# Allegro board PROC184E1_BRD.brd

Outline 248.76 x 190.5 mm; copper layers: TOP, L2-GND1, L3-SIGNAL1, L4-GND2, L5-SIGNAL2, L6-GND3, L7-SIGNAL3, L8-PWR1, L9-PWR2, L10-SIGNAL4, L11-GND4, L12-SIGNAL5, L13-GND5, L14-SIGNAL6, L15-GND6, BOTTOM. Coordinates in mm from the lower left corner of the outline.
Outline path: 5,190.5 0,190.5 0,0 5,0 ; 5,190.5 5,0 ; 5,190.5 16.79,190.5 17.29,190 17.29,188.93 arc(17.72,188.45) 18.19,188.9 18.19,190 18.69,190.5 21.54,190.5 22.04,190 22.04,188.89 arc(22.49,188.45) 22.94,188.9 22.94,190 23.44,190.5 243.76,190.5 ; 5,0 184.81,0 185.31,0.5 185.31,1.6 arc(185.76,2.05) 186.21,1.6 186.21,0.5 186.71,0 189.56,0 190.06,0.5 190.06,1.6 arc(190.51,2.05) 190.96,1.6 190.96,0.5 191.46,0 205.41,0 205.91,0.5 205.91,1.6 arc(206.36,2.05) 206.81,1.6 206.81,0.5 207.31,0 210.16,0 210.66,0.5 210.66,1.6 arc(211.11,2.05) 211.56,1.6 211.56,0.5 212.06,0 243.76,0 ; 243.76,0 243.76,190.5 ; 243.76,0 248.76,0 248.76,190.5 243.76,190.5

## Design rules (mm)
net group 33-OHM_PH: nets DDR0_CA1 DDR0_CA5
net group AOUT1: nets AOUT1_N AOUT1_P
net group AOUT2: nets AOUT2_N AOUT2_P
net group C_DP0_AUX_N: nets C_DP0_AUX_N DP0_AUX_N
net group C_DP0_AUX_P: nets C_DP0_AUX_P DP0_AUX_P
net group C_DP0_TX0_N: nets C_DP0_TX0_N DP0_TX0_N
net group C_DP0_TX0_P: nets C_DP0_TX0_P DP0_TX0_P
net group C_DP0_TX1_N: nets C_DP0_TX1_N DP0_TX1_N
net group C_DP0_TX1_P: nets C_DP0_TX1_P DP0_TX1_P
net group C_DP0_TX2_N: nets C_DP0_TX2_N DP0_TX2_N
net group C_DP0_TX2_P: nets C_DP0_TX2_P DP0_TX2_P
net group C_DP0_TX3_N: nets C_DP0_TX3_N DP0_TX3_N
net group C_DP0_TX3_P: nets C_DP0_TX3_P DP0_TX3_P
net group C_DP1_AUX_N: nets C_DP1_AUX_N DP1_AUX_N
net group C_DP1_AUX_P: nets C_DP1_AUX_P DP1_AUX_P
net group C_DP1_TX0_N: nets C_DP1_TX0_N DP1_TX0_N
net group C_DP1_TX0_P: nets C_DP1_TX0_P DP1_TX0_P
net group C_DP1_TX1_N: nets C_DP1_TX1_N DP1_TX1_N
net group C_DP1_TX1_P: nets C_DP1_TX1_P DP1_TX1_P
net group C_DP1_TX2_N: nets C_DP1_TX2_N DP1_TX2_N
net group C_DP1_TX2_P: nets C_DP1_TX2_P DP1_TX2_P
net group C_DP1_TX3_N: nets C_DP1_TX3_N DP1_TX3_N
net group C_DP1_TX3_P: nets C_DP1_TX3_P DP1_TX3_P
net group C_PCIE0_TX0_N: nets C_PCIE0_TX0_N PCIE0_TX0_N
net group C_PCIE0_TX0_P: nets C_PCIE0_TX0_P PCIE0_TX0_P
net group C_PCIE0_TX1_N: nets C_PCIE0_TX1_N PCIE0_TX1_N
net group C_PCIE0_TX1_P: nets C_PCIE0_TX1_P PCIE0_TX1_P
net group C_PCIE0_TX2_N: nets C_PCIE0_TX2_N PCIE0_TX2_N
net group C_PCIE0_TX2_P: nets C_PCIE0_TX2_P PCIE0_TX2_P
net group C_PCIE0_TX3_N: nets C_PCIE0_TX3_N PCIE0_TX3_N
net group C_PCIE0_TX3_P: nets C_PCIE0_TX3_P PCIE0_TX3_P
net group CLKGEN_PCIE0_4L_REFCLK_N: nets CDCI1_Y2N CLKGEN_PCIE0_4L_REFCLK_N
net group CLKGEN_PCIE0_4L_REFCLK_P: nets CDCI1_Y2P CLKGEN_PCIE0_4L_REFCLK_P
net group CLKGEN_PCIE1_2L_REFCLK_N: nets CDCI1_Y4N CLKGEN_PCIE1_2L_REFCLK_N
net group CLKGEN_PCIE1_2L_REFCLK_P: nets CDCI1_Y4P CLKGEN_PCIE1_2L_REFCLK_P
net group CLKGEN_SERDES0_REFCLK_N: nets CDCI1_Y3N CLKGEN_SERDES1_REFCLK_N
net group CLKGEN_SERDES0_REFCLK_P: nets CDCI1_Y3P CLKGEN_SERDES1_REFCLK_P
net group CLKGEN_SERDES1_REFCLK_N: nets CDCI1_Y1N CLKGEN_SERDES0_REFCLK_N
net group CLKGEN_SERDES1_REFCLK_P: nets CDCI1_Y1P CLKGEN_SERDES0_REFCLK_P
net group CON_DP0_AUX: nets CON_DP0_AUX_N CON_DP0_AUX_P
net group CON_DP0_TX0: nets CON_DP0_TX0_N CON_DP0_TX0_P
net group CON_DP0_TX1: nets CON_DP0_TX1_N CON_DP0_TX1_P
net group CON_DP0_TX2: nets CON_DP0_TX2_N CON_DP0_TX2_P
net group CON_DP0_TX3: nets CON_DP0_TX3_N CON_DP0_TX3_P
net group CON_DP1_AUX: nets CON_DP1_AUX_N CON_DP1_AUX_P
net group CON_DP1_TX0: nets CON_DP1_TX0_N CON_DP1_TX0_P
net group CON_DP1_TX1: nets CON_DP1_TX1_N CON_DP1_TX1_P
net group CON_DP1_TX2: nets CON_DP1_TX2_N CON_DP1_TX2_P
net group CON_DP1_TX3: nets CON_DP1_TX3_N CON_DP1_TX3_P
net group CONN_PCIE0_4L_REFCLK: nets CON_PCIE0_4L_REFCLK_N CON_PCIE0_4L_REFCLK_P
net group CONN_PCIE1_2L_REFCLK: nets CON_PCIE1_2L_REFCLK_N CON_PCIE1_2L_REFCLK_P
net group DDR0_CK: nets DDR0_CK_C DDR0_CK_T
net group DDR0_DQS0: nets DDR0_DQS0_N DDR0_DQS0_P
net group DDR0_DQS1: nets DDR0_DQS1_N DDR0_DQS1_P
net group DDR0_DQS2: nets DDR0_DQS2_N DDR0_DQS2_P
net group DDR0_DQS3: nets DDR0_DQS3_N DDR0_DQS3_P
net group DIFFPAIR15: nets AOUT1_A AOUT1_B
net group DIFFPAIR16: nets AOUT1N AOUT1P
net group DIFFPAIR17: nets AOUT2N AOUT2P
net group DIFFPAIR18: nets AOUT2_A AOUT2_B
net group DIFFPAIR23: nets USB_DM_FT2232 USB_DP_FT2232
net group DIFFPAIR24: nets USB_DM_FT4232 USB_DP_FT4232
net group DIFFPAIR42: nets USB0_DATA_N USB0_DATA_P
net group DP1: nets N24575373 N24575375
net group EXP_3V3_: nets EXP_3V3_N EXP_3V3_P
net group MCAN3: nets MCAN3_H MCAN3_L
net group MCAN4: nets MCAN4_H MCAN4_L
net group MCAN5: nets MCAN5_H MCAN5_L
net group MCAN16: nets MCAN16_H MCAN16_L
net group MCU_MCAN0_: nets MCU_MCAN0_H MCU_MCAN0_L
net group MCU_MCAN1_: nets MCU_MCAN1_H MCU_MCAN1_L
net group MCU_ONAND_DS: nets MCU_ONAND_DS R_MCU_ONAND_DS
net group MCU_OSPI0: nets MCU_OSPI0_CS0# MCU_OSPI0_LBCLKO
net group MCU_OSPI0_DQS: nets MCU_OSPI0_DQS OSPI_DQS_R
net group MCU_OSPI1_CLK: nets MCU_OSPI1_CLK MCU_OSPI1_CLK_R
net group MCU_OSPI1_DQS: nets MCU_OSPI1_DQS MCU_OSPI1_LBCLKO
net group MCU_RGMII1_RD0: nets MCU_RGMII1_RD0 MCU_RGMII1_RD0_R
net group MCU_RGMII1_RD1: nets MCU_RGMII1_RD1 MCU_RGMII1_RD1_R
net group MCU_RGMII1_RD2: nets MCU_RGMII1_RD2 MCU_RGMII1_RD2_R
net group MCU_RGMII1_RD3: nets MCU_RGMII1_RD3 MCU_RGMII1_RD3_R
net group MCU_RGMII1_RX_CTL: nets MCU_RGMII1_RX_CTL MCU_RGMII1_RX_CTL_R
net group MCU_RGMII1_RXC: nets MCU_RGMII1_RXC MCU_RGMII1_RXC_R
net group MIC1_L: nets MIC1_L_N MIC1_L_P
net group MIC1_R: nets MIC1_R_N MIC1_R_P
net group MMC0_DS: nets MMC0_DS MMC0_DS_R
net group MMC1_CLK: nets MMC1_CLK MMC1_CLK_R
net group PCIE_REFCLK0_OUT: nets PCIE_REFCLK0_OUT_N PCIE_REFCLK0_OUT_P
net group PCIE_REFCLK1_OUT: nets PCIE_REFCLK1_OUT_N PCIE_REFCLK1_OUT_P
net group PCIE_REFCLK2_OUT: nets PCIE_REFCLK2_OUT_N PCIE_REFCLK2_OUT_P
net group PCIE_REFCLK3_OUT: nets PCIE_REFCLK3_OUT_N PCIE_REFCLK3_OUT_P
net group R_SERDES1_REFCLK: nets R_SERDES0_REFCLK_N R_SERDES0_REFCLK_P
net group R_SOC_SERDES0_REFCLK: nets R_SOC_SERDES0_REFCLK_N R_SOC_SERDES0_REFCLK_P
net group R_SOC_SERDES1_REFCLK: nets R_SOC_SERDES1_REFCLK_N R_SOC_SERDES1_REFCLK_P
net group R_SOC_SERDES4_REFCLK: nets R_SOC_SERDES4_REFCLK_N R_SOC_SERDES4_REFCLK_P
net group R_USB0_DATA: nets R_USB0_DATA_N R_USB0_DATA_P
net group RGMII1_RD0: nets RGMII1_RD0 RGMII1_RD0_R
net group RGMII1_RD1: nets RGMII1_RD1 RGMII1_RD1_R
net group RGMII1_RD2: nets RGMII1_RD2 RGMII1_RD2_R
net group RGMII1_RD3: nets RGMII1_RD3 RGMII1_RD3_R
net group RGMII1_RX_CTL: nets RGMII1_RX_CTL RGMII1_RX_CTL_R
net group RGMII1_RXC: nets RGMII1_RXC RGMII1_RXC_R
net group SERDES0_REFCLK_R: nets R_SERDES1_REFCLK_N R_SERDES1_REFCLK_P
net group SOC_MCU_OSPI0_CLK: nets SOC_MCU_OSPI0_CLK SOC_MCU_OSPI0_CLK_R
net group SOC_SERDES0_REFCLK: nets SOC_SERDES0_REFCLK_N SOC_SERDES0_REFCLK_P
net group SOC_SERDES1_REFCLK: nets SOC_SERDES1_REFCLK_N SOC_SERDES1_REFCLK_P
net group SOC_SERDES4_REFCLK_N: nets CDCI2_Y2N SOC_SERDES4_REFCLK_N
net group SOC_SERDES4_REFCLK_P: nets CDCI2_Y2P SOC_SERDES4_REFCLK_P
net group USB0_D: nets USB0_D_N USB0_D_P
net group USB0_DATA_MUX: nets MUX_USB0_DATA_N MUX_USB0_DATA_P
net group USB0_DATA_MUX_R: nets R_MUX_USB0_DATA_N R_MUX_USB0_DATA_P
net group USB1_DN1_D: nets USB1_DN1_D_N USB1_DN1_D_P
net group USB1_DN2_D: nets USB1_DN2_D_N USB1_DN2_D_P
net group USB1_DN3_D: nets USB1_DN3_D_N USB1_DN3_D_P
net group USB1_DN4_D: nets USB1_DN4_D_N USB1_DN4_D_P
net group USB1_HUB_D: nets USB1_HUB_D_N USB1_HUB_D_P
net group USB_CONN#1_D: nets USB_CONN#1_D_N USB_CONN#1_D_P
net group USB_CONN#2_D: nets USB_CONN#2_D_N USB_CONN#2_D_P
net group USBC_DATA_CONN: nets USBC_DATA_CONN_N USBC_DATA_CONN_P
net group USBC_SS_RX1_N: nets USBC_SS_RX1_CONN_N USBC_SS_RX1_N
net group USBC_SS_RX1_P: nets USBC_SS_RX1_CONN_P USBC_SS_RX1_P
net group USBC_SS_RX2_N: nets USBC_SS_RX2_CONN_N USBC_SS_RX2_N
net group USBC_SS_RX2_P: nets USBC_SS_RX2_CONN_P USBC_SS_RX2_P
net group USBC_SS_TX1_N: nets USBC_SS_TX1_CONN_N USBC_SS_TX1_N
net group USBC_SS_TX1_P: nets USBC_SS_TX1_CONN_P USBC_SS_TX1_P
net group USBC_SS_TX2_N: nets USBC_SS_TX2_CONN_N USBC_SS_TX2_N
net group USBC_SS_TX2_P: nets USBC_SS_TX2_CONN_P USBC_SS_TX2_P
net group XDS_USB_D: nets XDS_USB_D_N XDS_USB_D_P
net group 40-OHM_PH: nets DDR0_CKE0 DDR0_DM0_DBI0# DDR0_DM1_DBI1# DDR0_DM2_DBI2# DDR0_DM3_DBI3# DDR0_DQ0 DDR0_DQ1 DDR0_DQ2 DDR0_DQ4 DDR0_DQ14 DDR0_DQ15 DDR0_DQ18 DDR0_DQ20 DDR0_DQ21 DDR0_DQ24 DDR0_DQ26 DDR0_DQ27 DDR0_DQ28
net group 50-OHM_PH: nets DDR0_CAL0 DDR0_ODT_CA_A DDR0_ODT_CA_B DDR0_RET DDR0_RST# DDR0_ZQ0 DDR0_ZQ1 DDR1_CAL0 DDR1_ODT_CA_B DDR1_RET DDR1_RST# DDR1_ZQ0 DDR1_ZQ1
net group CSI0: nets CSI0_RXCLK_N
net group CSI1: nets CSI1_RXCLK_N
net group DDR0_CA: nets DDR0_CA0 DDR0_CA2 DDR0_CA3 DDR0_CA4 DDR0_CKE1 DDR0_CSN0_0 DDR0_CSN0_1 DDR0_CSN1_0 DDR0_CSN1_1
net group DDR0_DL0: nets DDR0_DQ3 DDR0_DQ5 DDR0_DQ6 DDR0_DQ7
net group DDR0_DL1: nets DDR0_DQ8 DDR0_DQ9 DDR0_DQ10 DDR0_DQ11 DDR0_DQ12 DDR0_DQ13
net group DDR0_DL2: nets DDR0_DQ16 DDR0_DQ17 DDR0_DQ19 DDR0_DQ22 DDR0_DQ23
net group DDR0_DL3: nets DDR0_DQ25 DDR0_DQ29 DDR0_DQ30 DDR0_DQ31
net group DDR1_CA: nets DDR1_CSN0_0 DDR1_CSN0_1 DDR1_CSN1_0 DDR1_CSN1_1
net group DDR1_DL0: nets DDR1_DM0_DBI0# DDR1_DQ0 DDR1_DQ1 DDR1_DQ2 DDR1_DQ3 DDR1_DQ4 DDR1_DQ5 DDR1_DQ6 DDR1_DQ7 DDR1_DQS0_N DDR1_DQS0_P
net group DDR1_DL1: nets DDR1_DM1_DBI1# DDR1_DQ8 DDR1_DQ9 DDR1_DQ10 DDR1_DQ11 DDR1_DQ12 DDR1_DQ13 DDR1_DQ14 DDR1_DQ15 DDR1_DQS1_N DDR1_DQS1_P
net group DDR1_DL2: nets DDR1_DM2_DBI2# DDR1_DQ16 DDR1_DQ17 DDR1_DQ18 DDR1_DQ19 DDR1_DQ20 DDR1_DQ21 DDR1_DQ22 DDR1_DQ23 DDR1_DQS2_N DDR1_DQS2_P
net group DDR1_DL3: nets DDR1_DM3_DBI3# DDR1_DQ24 DDR1_DQ25 DDR1_DQ26 DDR1_DQ27 DDR1_DQ28 DDR1_DQ29 DDR1_DQ30 DDR1_DQ31 DDR1_DQS3_N DDR1_DQS3_P
net group GESI_RMII8_RX: nets GESI_RMII8_RX_ER GESI_RMII8_RXD0 GESI_RMII8_RXD1
net group GESI_RMII8_TX: nets GESI_RMII8_TX_EN GESI_RMII8_TXD0 GESI_RMII8_TXD1
net group MCU_ADC1_AIN0-7: nets MCU_ADC1_AIN0 MCU_ADC1_AIN1 MCU_ADC1_AIN2 MCU_ADC1_AIN3 MCU_ADC1_AIN4 MCU_ADC1_AIN5 MCU_ADC1_AIN6 MCU_ADC1_AIN7
net group MCU_OSPI1: nets MCU_OSPI1_CS0
net group MCU_RGMII1: nets RGMII1_RESET_N
net group OSPI0: nets SOC_MCU_OSPI0_D0 SOC_MCU_OSPI0_D1 SOC_MCU_OSPI0_D2 SOC_MCU_OSPI0_D3 SOC_MCU_OSPI0_D4 SOC_MCU_OSPI0_D5 SOC_MCU_OSPI0_D6 SOC_MCU_OSPI0_D7 SOC_MCU_OSPI0_DQS
net group OSPI1: nets MCU_OSPI1_D0 MCU_OSPI1_D1 MCU_OSPI1_D2 MCU_OSPI1_D3
net group PCIE0_RX_DIFF: nets PCIE0_RX0_N PCIE0_RX0_P PCIE0_RX1_N PCIE0_RX1_P PCIE0_RX2_N PCIE0_RX2_P PCIE0_RX3_N PCIE0_RX3_P
net group PCIE1/HYP0_RX: nets PCIE1/HYP0_RX0_N PCIE1/HYP0_RX0_P PCIE1/HYP0_RX1_N PCIE1/HYP0_RX1_P PCIE1/HYP0_RX2_N PCIE1/HYP0_RX2_P PCIE1/HYP0_RX3_N PCIE1/HYP0_RX3_P SERDES0_RX2_N SERDES0_RX2_P SERDES0_RX3_N SERDES0_RX3_P
net group PCIE1/HYP0_TX: nets C_PCIE1/HYP0_TX0_N C_PCIE1/HYP0_TX0_P C_PCIE1/HYP0_TX1_N C_PCIE1/HYP0_TX1_P PCIE1/HYP0_TX0_N PCIE1/HYP0_TX0_P PCIE1/HYP0_TX1_N PCIE1/HYP0_TX1_P PCIE1/HYP0_TX2_N PCIE1/HYP0_TX2_P PCIE1/HYP0_TX3_N PCIE1/HYP0_TX3_P SERDES0_TX2_N SERDES0_TX2_P SERDES0_TX3_N SERDES0_TX3_P
net group POWER: nets VCC_12V0
net group PWR: nets N35604832 VCCA_3V3 VDD1_DDR_1V8 VDD_DDR_1V1
net group PWR_PH: nets VDA_PLL_1V8_REG
net group R_RGMII1_RX: nets R_RGMII1_RD0 R_RGMII1_RD1 R_RGMII1_RD2 R_RGMII1_RD3 R_RGMII1_RX_CTL R_RGMII1_RXC
net group R_RGMII1_TX: nets R_RGMII1_TD0 R_RGMII1_TD1 R_RGMII1_TD2 R_RGMII1_TD3 R_RGMII1_TX_CTL R_RGMII1_TXC
net group SOC_MCU_OSPI0: nets SOC_MCU_OSPI0_CS0#
net group UFS_DIFF: nets UFS0_RX0_N UFS0_RX0_P UFS0_RX1_N UFS0_RX1_P UFS0_TX0_N UFS0_TX0_P UFS0_TX1_N UFS0_TX1_P

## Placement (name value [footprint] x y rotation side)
ACC*  -  [unnamed#3]  120.72 81.43 180 top
B1  BC501SM  [BATTH_BC501SM_580X590_SMD_4-2]  150.43 27.93 270 bottom
C1  1uF  [CAP0402_0-75]  181.56 188.91 0 top
C2  1000pF  [CAP1206_1-75]  157.58 188.55 180 top
C3  22uF  [CAP0805_1-5]  165.87 188.24 180 top
C4  22uF  [CAP0805_1-5]  172.79 184.16 0 top
C5  22uF  [CAP0805_1-5]  172.79 182.13 0 top
C6  0.1uF  [CAP0402_0-75]  175.52 181.24 0 top
C7  0.1uF  [CAP0402_0-75]  181.54 180.26 180 top
C8  2.2uF  [CAP0402_0-75]  175.52 180.1 180 top
C9  22uF  [CAP0805_1-5]  168.96 179.33 270 top
C10  22uF  [CAP0805_1-5]  170.99 179.33 270 top
C11  0.1uF  [CAP0402_0-75]  56.35 178.8 0 top
C12  0.1uF  [CAP0402_0-75]  59.7 178.29 180 top
C13  2.2uF  [CAP0402_0-75]  24.11 178.22 90 top
C14  0.1uF  [CAP0402_0-75]  21.36 177.96 90 top
C15  0.1uF  [CAP0402_0-75]  16.66 177.96 270 top
C16  2.2uF  [CAP0402_0-75]  18.82 177.95 90 top
C17  1uF  [CAP0402_0-75]  20.09 177.95 90 top
C18  0.1uF  [CAP0402_0-75]  12.84 177.49 270 top
C19  10uF  [CAP0603_1-25]  59.71 176.62 180 top
C20  0.1uF  [CAP0402_0-75]  181.29 176.1 180 top
C21  0.1uF  [CAP0402_0-75]  46.77 175.65 180 top
C22  0.1uF  [CAP0402_0-75]  100.85 174.84 0 top
C23  0.1uF  [CAP0402_0-75]  126.59 174.84 0 top
C24  1uF  [CAP0402_0-75]  26.37 173.98 0 top
C25  150uF_10V  [CAPT7343D_3-25]  55.69 173.39 270 top
C26  10uF  [CAP0603_1-25]  168.03 173.23 90 top
C27  0.1uF  [CAP0402_0-75]  170.54 173.23 270 top
C28  15uF  [CAP2220_2-75]  163.92 172.97 90 top
C29  15pF  [CAP0402_0-75]  29.29 172.86 0 top
C30  0.1uF  [CAP0402_0-75]  75.05 171.97 270 top
C31  1uF  [CAP0402_0-75]  11.31 170.85 270 top
C32  150uF_10V  [CAPT7343D_3-25]  49.13 170.37 270 top
C33  0.1uF  [CAP0402_0-75]  43.42 169.68 0 top
C34  0.1uF  [CAP0402_0-75]  33.39 169.65 0 top
C35  0.1uF  [CAP0402_0-75]  140.52 169.2 90 top
C36  0.1uF  [CAP0402_0-75]  79.17 169.07 0 top
C37  0.22uF  [CAP0201_0-5]  115.64 168.46 90 top
C38  0.22uF  [CAP0201_0-5]  116.4 168.46 90 top
C39  0.22uF  [CAP0201_0-5]  121.58 168.46 90 top
C40  0.22uF  [CAP0201_0-5]  122.35 168.46 90 top
C41  0.1uF  [CAP0402_0-75]  75.36 168.18 0 top
C42  10uF  [CAP0805_1-5]  43.42 167.9 0 top
C43  0.1uF  [CAP0402_0-75]  11.5 167.75 180 top
C44  0.22uF  [CAP0201_0-5]  112.71 167.06 90 top
C45  0.22uF  [CAP0201_0-5]  113.48 167.06 90 top
C46  0.22uF  [CAP0201_0-5]  118.58 166.81 90 top
C47  0.22uF  [CAP0201_0-5]  119.34 166.81 90 top
C48  0.1uF  [CAP0402_0-75]  27.01 166.47 90 top
C49  0.1uF  [CAP0402_0-75]  57.41 165.77 90 top
C50  0.1uF  [CAP0402_0-75]  19.6 165.74 180 top
C51  0.22uF  [CAP0201_0-5]  124.63 165.18 90 top
C52  0.22uF  [CAP0201_0-5]  125.39 165.18 90 top
C53  2.2uF  [CAP1210_2-75]  211.55 164.62 90 top
C54  0.01uF  [CAP0402_0-75]  19.6 164.6 180 top
C55  0.1uF  [CAP0402_0-75]  127.82 164.58 270 top
C58  0.1uF  [CAP0402_0-75]  175.73 162.69 90 top
C59  1uF  [CAP0402_0-75]  21.21 162.53 90 top
C60  0.01uF  [CAP0402_0-75]  19.95 162.52 90 top
C63  0.1uF  [CAP0402_0-75]  35.31 162.44 180 top
C64  0.1uF  [CAP0402_0-75]  131.57 162.34 270 top
C66  0.1uF  [CAP0402_0-75]  35.31 161.3 180 top
C67  0.47uF  [CAP0402_0-75]  113.98 160.79 0 top
C68  0.1uF  [CAP0402_0-75]  158.94 160.12 270 top
C69  0.1uF  [CAP0402_0-75]  160.09 160.12 270 top
C70  0.1uF  [CAP0402_0-75]  161.23 160.12 270 top
C71  4.7uF  [CAP0402_0-75]  113.98 159.65 0 top
C72  4.7uF  [CAP0402_0-75]  103.69 159.45 90 top
C73  0.47uF  [CAP0402_0-75]  104.83 159.45 90 top
C74  0.1uF  [CAP0402_0-75]  105.98 159.45 270 top
C75  1uF  [CAP0402_0-75]  88.07 159.16 180 top
C76  27pF  [CAP0402_0-75]  69.2 158.91 0 top
C77  27pF  [CAP0402_0-75]  71.23 158.91 180 top
C78  27pF  [CAP0402_0-75]  92.01 158.86 0 top
C79  27pF  [CAP0402_0-75]  94.04 158.86 180 top
C80  100uF_160V  [CAPAE_CASE173173_22-5]  232.76 158.78 0 top
C81  0.1uF  [CAP0402_0-75]  113.98 158.51 180 top
C82  0.1uF  [CAP0402_0-75]  164.85 158.25 0 top
C83  0.01uF  [CAP0402_0-75]  88.07 158.02 180 top
C84  100uF  [CAP1210_2-75]  173.08 157.97 0 top
C85  4.7uF  [CAP0402_0-75]  103.69 157.41 270 top
C86  0.47uF  [CAP0402_0-75]  104.83 157.41 270 top
C87  0.1uF  [CAP0402_0-75]  105.98 157.41 90 top
C88  5600pF  [CAP0402_0-75]  207.58 157.21 90 top
C89  0.1uF  [CAP0402_0-75]  88.07 156.88 180 top
C90  27pF  [CAP0402_0-75]  114.49 156.85 270 top
C91  0.1uF  [CAP0402_0-75]  127.31 156.78 0 top
C92  22uF_100V  [CAPAE_CASE8383_10-5]  181.62 156.34 90 top
C93  0.1uF  [CAP0402_0-75]  14.65 155.68 270 top
C94  33pF  [CAP0402_0-75]  204.61 155.51 180 top
C95  390pF  [CAP0402_0-75]  206.31 155.4 90 top
C96  1uF  [CAP0402_0-75]  87.18 154.98 90 top
C97  0.1uF  [CAP0402_0-75]  88.32 154.98 90 top
C98  0.1uF  [CAP0402_0-75]  112.71 154.95 180 top
C99  27pF  [CAP0402_0-75]  114.49 154.95 90 top
C100  0.1uF  [CAP0402_0-75]  200.54 154.8 0 top
C101  100uF  [CAP1210_2-75]  173.08 154.16 0 top
C102  4.7uF  [CAP0402_0-75]  112.71 153.81 0 top
C103  0.01uF  [CAP0402_0-75]  209.48 153.19 90 top
C104  0.47uF  [CAP0402_0-75]  112.71 152.66 0 top
C105  0.1uF  [CAP0402_0-75]  98.23 152.43 0 top
C106  4.7uF  [CAP1206_2]  188.44 151.75 0 top
C107  2.2uF  [CAP0402_0-75]  137.93 151.54 90 top
C108  2.2uF  [CAP0402_0-75]  198.51 151.37 270 top
C109  0.01uF  [CAP0402_0-75]  87.05 150.7 270 top
C110  0.1uF  [CAP0402_0-75]  88.32 150.7 270 top
C111  0.47uF  [CAP0402_0-75]  208.72 150.38 180 top
C112  100uF  [CAP1210_2-75]  173.08 150.35 0 top
C113  1uF  [CAP0402_0-75]  137.93 149.54 270 top
C114  2.2uF  [CAP0402_0-75]  198.51 149.33 90 top
C115  0.1uF  [CAP0402_0-75]  11.83 138.99 180 top
C116  4.7uF  [CAP1206_2]  188.44 148.95 0 top
C117  0.47uF  [CAP0402_0-75]  208.72 148.6 0 top
C118  10uF  [CAP0603_1-25]  18.89 148.35 270 top
C119  2.2uF  [CAP0402_0-75]  137.93 147.36 270 top
C120  100uF  [CAP1210_2-75]  173.08 146.54 0 top
C121  33pF  [CAP0402_0-75]  204.49 145.68 0 top
C122  0.1uF  [CAP0402_0-75]  200.16 145.65 180 top
C123  0.1uF  [CAP0402_0-75]  207.12 145.3 270 top
C124  22uF_100V  [CAPAE_CASE8383_10-5]  181.62 144.36 270 top
C125  0E  [RES0402_0-5]  32.63 143.63 270 top
C126  100uF  [CAP1210_2-75]  173.08 142.73 0 top
C129  0E  [RES0402_0-5]  32.63 141.65 90 top
C130  100uF_160V  [CAPAE_CASE173173_22-5]  232.6 137.83 0 top
C134  10uF  [CAP0805_1-5]  101.92 136.78 90 top
C136  0.1uF  [CAP0402_0-75]  103.52 133.76 270 top
C137  0.1uF  [CAP0402_0-75]  105.03 133.76 270 top
C138  0.1uF  [CAP0402_0-75]  106.88 133.76 270 top
C139  0.1uF  [CAP0402_0-75]  108.02 133.76 90 top
C140  0.1uF  [CAP0402_0-75]  109.17 133.76 270 top
C141  0.1uF  [CAP0402_0-75]  111.02 133.76 270 top
C142  0.1uF  [CAP0402_0-75]  112.97 133.47 90 top
C143  0.1uF  [CAP0402_0-75]  13.65 132.95 270 top
C144  0.1uF  [CAP0402_0-75]  14.92 132.95 270 top
C145  0.1uF  [CAP0402_0-75]  201.86 132.31 0 top
C146  0.1uF  [CAP0402_0-75]  203.92 132.31 0 top
C147  0.1uF  [CAP0402_0-75]  112.97 129.81 0 top
C148  0.1uF  [CAP0402_0-75]  112.97 126.81 180 top
C149  22uF  [CAP0805_1-5]  29.54 126.69 180 top
C150  0.1uF  [CAP0402_0-75]  203.79 125.74 270 top
C151  0.1uF  [CAP0402_0-75]  112.97 125.63 180 top
C152  0.1uF  [CAP0402_0-75]  101.57 124.81 180 top
C153  0.1uF  [CAP0402_0-75]  112.97 124.49 0 top
C154  10pF  [CAP0402_0-75]  179.08 124.42 270 top
C155  3300pF  [CAP0402_0-75]  167.88 124.38 270 top
C156  10pF  [CAP0402_0-75]  190.46 124.37 270 top
C157  0.1uF  [CAP0402_0-75]  101.57 123.8 0 top
C158  10pF  [CAP0402_0-75]  166.27 123.79 0 top
C159  1uF  [CAP0402_0-75]  112.97 123.35 180 top
C160  0.1uF  [CAP0402_0-75]  19.26 123.3 90 top
C161  0.1uF  [CAP0402_0-75]  45.73 123.09 90 top
C162  27pF  [CAP0402_0-75]  59.87 121.95 0 top
C163  27pF  [CAP0402_0-75]  61.78 121.95 180 top
C164  0.47uF  [CAP0402_0-75]  55.94 121.44 90 top
C165  4.7uF  [CAP0402_0-75]  57.08 121.44 90 top
C166  0.1uF  [CAP0402_0-75]  58.22 121.44 270 top
C167  0.1uF  [CAP0402_0-75]  61.78 120.17 270 top
C168  4.7uF  [CAP0402_0-75]  62.92 120.17 90 top
C169  0.47uF  [CAP0402_0-75]  64.07 120.17 90 top
C170  22uF  [CAP0805_1-5]  31.11 119.15 0 top
C171  10pF  [CAP0402_0-75]  72.96 118.9 0 top
C172  220uF_6.3V  [CAPAE_B6CASE_6]  203.84 118.3 270 top
C173  220uF_6.3V  [CAPAE_B6CASE_6]  210.19 118.3 270 top
C174  220uF_6.3V  [CAPAE_B6CASE_6]  216.54 118.3 270 top
C175  47uF  [CAP1210_2-75]  79.82 117.63 180 top
C176  1uF  [CAP0603_1]  107.15 117.19 270 top
C177  0.1uF  [CAP0402_0-75]  48.91 116.71 180 top
C178  47uF  [CAP1210_2-75]  165.72 115.29 90 top
C179  47uF  [CAP1210_2-75]  173.59 115.29 90 top
C180  47uF  [CAP1210_2-75]  177.15 115.29 90 top
C181  47uF  [CAP1210_2-75]  185.02 115.29 90 top
C182  47uF  [CAP1210_2-75]  188.32 115.29 90 top
C183  47uF  [CAP1210_2-75]  196.2 115.29 90 top
C184  0.1uF  [CAP0402_0-75]  48.94 114.72 90 top
C185  1uF  [CAP0603_1]  107.15 114.65 90 top
C186  0.1uF  [CAP0402_0-75]  57.28 113.57 0 top
C187  0.1uF  [CAP0402_0-75]  59.32 113.57 180 top
C188  0.1uF  [CAP0402_0-75]  49.27 113.09 180 top
C189  3300pF  [CAP0402_0-75]  70.72 112.55 0 top
C190  0.47uF  [CAP0402_0-75]  57.28 112.43 180 top
C191  0.47uF  [CAP0402_0-75]  59.32 112.43 0 top
C192  0.01uF  [CAP0402_0-75]  109.06 112.39 0 top
C193  100uF  [CAP1210_3]  95.56 111.79 0 top
C194  0.015uF  [CAP0805_1]  210.8 111.79 90 top
C195  2200pF  [CAP0805_1-5]  212.96 111.79 90 top
C196  4.7uF  [CAP0402_0-75]  57.28 111.28 180 top
C197  4.7uF  [CAP0402_0-75]  59.32 111.28 0 top
C198  10pF  [CAP0402_0-75]  71.23 111.03 90 top
C199  22uF_100V  [CAPAE_CASE8383_10-5]  238.16 110.47 90 top
C200  47uF  [CAP1210_2-75]  79.82 109.76 180 top
C201  0.1uF  [CAP0402_0-75]  219.91 109.65 0 top
C202  33pF  [CAP0402_0-75]  215.22 109.41 180 top
C203  100uF  [CAP1210_3]  95.56 108.49 0 top
C204  1uF  [CAP0402_0-75]  24.96 107.44 0 top
C205  0.056uF  [CAP1206_1-25]  208.82 107.2 270 top
C206  100uF  [CAP1210_3]  116.01 106.97 270 top
C207  100uF  [CAP1210_3]  119.57 106.97 270 top
C208  100uF  [CAP1210_3]  123.12 106.97 270 top
C209  100uF  [CAP1210_3]  126.68 106.97 270 top
C210  100uF  [CAP1210_3]  130.23 106.97 270 top
C211  100uF  [CAP1210_3]  133.79 106.97 270 top
C212  100uF  [CAP1210_3]  137.35 106.97 270 top
C213  100uF  [CAP1210_3]  140.9 106.97 270 top
C214  100uF  [CAP1210_3]  144.46 106.97 270 top
C215  100uF  [CAP1210_3]  148.01 106.97 270 top
C216  0.1uF  [CAP0402_0-75]  29.61 106.59 90 top
C217  1uF  [CAP0402_0-75]  211.13 106.54 180 top
C218  47uF  [CAP1210_2-75]  79.82 106.46 180 top
C219  1uF  [CAP0402_0-75]  221.26 105.8 270 top
C220  100uF  [CAP1210_3]  95.56 105.19 0 top
C221  1uF  [CAP0402_0-75]  211.13 104.54 0 top
C222  1uF  [CAP0402_0-75]  221.26 103.77 90 top
C223  0.056uF  [CAP1206_1-25]  208.82 102.37 90 top
C224  0.1uF  [CAP0402_0-75]  62.84 102.19 0 top
C225  100uF  [CAP1210_3]  95.56 101.89 0 top
C226  10pF  [CAP0402_0-75]  70.8 101.38 0 top
C227  1uF  [CAP0402_0-75]  148.65 101.25 0 top
C228  10uF  [CAP0603_1]  151.44 101.25 180 top
C229  0.01uF  [CAP0402_0-75]  153.98 101.25 0 top
C230  10uF  [CAP0603_1]  156.65 101.25 180 top
C231  0.1uF  [CAP0402_0-75]  62.84 101.05 0 top
C232  0.1uF  [CAP0402_0-75]  219.53 100.18 180 top
C233  0.1uF  [CAP0402_0-75]  62.84 99.91 0 top
C234  33pF  [CAP0402_0-75]  215.27 99.78 0 top
C235  22uF_100V  [CAPAE_CASE8383_10-5]  238.16 98.79 270 top
C236  47uF  [CAP1210_2-75]  79.82 98.58 180 top
C237  100uF  [CAP1210_3]  95.56 98.58 0 top
C238  2700pF  [CAP0805_1-5]  211.38 97.26 270 top
C239  27pF  [CAP0805_0-75]  213.72 97.26 270 top
C240  0.1uF  [CAP0402_0-75]  160.97 96.55 270 top
C241  0.1uF  [CAP0402_0-75]  196.53 90.23 180 top
C242  0.1uF  [CAP0402_0-75]  196.53 89.08 180 top
C243  100uF  [CAP1210_3]  93.62 92.53 270 top
C244  0.1uF  [CAP0402_0-75]  196.53 87.94 180 top
C245  1uF  [CAP0603_1]  69.6 90.84 270 top
C246  10uF  [CAP0603_1-25]  71 90.84 270 top
C247  2.2uF  [CAP0603_1]  76.34 89.87 180 top
C248  180uF_16V  [CAPAE_C6CASE_6]  233.66 89.24 0 top
C249  0.01uF  [CAP0402_0-75]  97.37 87.93 180 top
C250  0.1uF  [CAP0402_0-75]  192.23 84.75 270 top
C251  0.1uF  [CAP0402_0-75]  192.23 82.68 270 top
C252  0.1uF  [CAP0402_0-75]  229.83 84.46 90 top
C253  47uF  [CAP1210_2-75]  173.16 84.23 0 top
C254  47uF  [CAP1210_2-75]  179 84.23 180 top
C255  220pF  [CAP0402_0-75]  81.77 82.74 0 top
C256  1uF  [CAP0603_1]  85.48 82.76 180 top
C257  0.1uF  [CAP0402_0-75]  192.23 80.72 270 top
C258  0.1uF  [CAP0402_0-75]  78.82 81.73 270 top
C259  10uF  [CAP0603_1-25]  37.49 80.79 180 top
C260  10uF  [CAP0805_1-5]  174.3 80.68 0 top
C261  10uF  [CAP0805_1-5]  177.86 80.68 180 top
C262  12pF  [CAP0402_0-75]  115.71 58.79 180 top
C263  0.1uF  [CAP0402_0-75]  192.23 78.65 270 top
C264  1uF  [CAP0603_1]  78.7 79.52 90 top
C265  1uF  [CAP0603_1]  87.22 79.52 90 top
C266  0.1uF  [CAP0402_0-75]  83.04 79.13 90 top
C267  2.2uF  [CAP0603_1]  169.66 78.14 180 top
C268  12pF  [CAP0402_0-75]  119.85 61.49 0 top
C269  0.1uF  [CAP0402_0-75]  192.23 76.68 270 top
C270  12pF  [CAP0402_0-75]  111.03 63.2 180 top
C271  2.2uF  [CAP0603_1]  169.66 76.49 180 top
C272  0.1uF  [CAP0402_0-75]  192.23 74.62 270 top
C273  47uF  [CAP1210_2-75]  185.61 75.6 90 top
C274  0.01uF  [CAP0402_0-75]  82.77 75.32 180 top
C275  0.1uF  [CAP0402_0-75]  160.97 75.22 270 top
C276  1uF  [CAP0603_1]  90.48 75.09 90 top
C277  2.2uF  [CAP0603_1]  169.66 75.09 180 top
C278  10uF  [CAP0805_1-5]  182.79 75.09 90 top
C279  12pF  [CAP0402_0-75]  114.13 59.51 270 top
C280  100uF_160V  [CAPAE_CASE173173_22-5]  213.98 74.2 0 top
C281  2.2uF  [CAP0603_1]  169.66 73.57 180 top
C282  1uF  [CAP0603_1]  77.48 73.18 0 top
C283  1uF  [CAP0603_1]  80.09 73.18 180 top
C284  1uF  [CAP0603_1]  86.8 73.18 0 top
C285  22uF  [CAP0805_1-25]  96.07 73.18 180 top
C286  2.2uF  [CAP0603_1]  169.66 72.04 180 top
C287  0.1uF  [CAP0402_0-75]  206.04 60.94 90 bottom
C288  2.2uF  [CAP0603_1]  169.66 70.52 180 top
C289  0.1uF  [CAP0402_0-75]  27.85 70.44 90 top
C290  47uF  [CAP1206_2]  226.91 69.07 180 top
C291  1uF  [CAP0603_1]  81.05 68.87 0 top
C292  0.1uF  [CAP0402_0-75]  83.37 68.87 180 top
C293  10uF  [CAP0805_1-5]  174.3 67.47 0 top
C294  10uF  [CAP0805_1-5]  177.86 67.47 180 top
C295  47uF  [CAP1206_2]  226.91 66.53 0 top
C296  0.1uF  [CAP0402_0-75]  79.85 65.01 180 top
C297  220pF  [CAP0402_0-75]  84.65 64.44 270 top
C298  47uF  [CAP1210_2-75]  179 63.74 180 top
C299  47uF  [CAP1210_2-75]  173.16 63.66 0 top
C300  0.1uF  [CAP0402_0-75]  192.85 62.95 90 top
C301  0.1uF  [CAP0603_1]  206.77 61.42 180 top
C302  0.1uF  [CAP0402_0-75]  210.33 59.28 270 top
C303  0.1uF  [CAP0402_0-75]  21.13 59.09 270 top
C304  0.1uF  [CAP0402_0-75]  28.57 58.86 270 top
C305  2700pF  [CAP0402_0-75]  200.69 58.78 270 top
C306  2.7pF  [CAP0402_0-75]  202.47 58.15 180 top
C307  0.1uF  [CAP0201_0-5]  142.17 57.31 0 top
C308  2.2uF  [CAP0402_0-75]  210.33 57.12 270 top
C309  1uF  [CAP0402_0-75]  148.65 57.06 0 top
C310  0.01uF  [CAP0402_0-75]  153.98 57.06 0 top
C311  10uF  [CAP0603_1]  151.44 56.93 0 top
C312  10uF  [CAP0603_1]  156.65 56.93 180 top
C313  0.1uF  [CAP0402_0-75]  124.29 44.51 270 bottom
C314  0.12uF  [CAP0603_1]  202.47 56.75 180 top
C315  0.1uF  [CAP0201_0-5]  142.17 56.42 0 top
C316  0.1uF  [CAP0402_0-75]  196.66 56.32 270 top
C317  0.1uF  [CAP0402_0-75]  187.15 56.31 270 top
C318  0.22uF  [CAP0402_0-75]  203.23 53.73 270 top
C319  1uF  [CAP0603_1]  157.29 53.63 0 top
C320  1uF  [CAP0603_1]  159.83 53.63 180 top
C321  0.1uF  [CAP0402_0-75]  205.51 53.6 90 top
C322  0.1uF  [CAP0402_0-75]  126.07 41.26 180 bottom
C323  0.1uF  [CAP0201_0-5]  170.87 52.54 0 top
C324  0.1uF  [CAP0402_0-75]  188.65 53 270 top
C325  4.7uF  [CAP0402_0-75]  130.89 40.57 90 bottom
C326  0.1uF  [CAP0402_0-75]  123.15 40.57 90 bottom
C327  4.7uF  [CAP0402_0-75]  118.32 41.26 180 bottom
C328  0.1uF  [CAP0201_0-5]  169.33 52.54 0 top
C329  0.01uF  [CAP0402_0-75]  199.24 98.67 0 top
C330  0.1uF  [CAP0201_0-5]  176.07 52.06 180 top
C331  2.2uF  [CAP0603_1]  173.54 52.03 0 top
C334  0.01uF  [CAP0402_0-75]  155.51 51.85 270 top
C335  0.1uF  [CAP0201_0-5]  182.47 51.63 270 top
C336  0.1uF  [CAP0201_0-5]  176.06 51.2 180 top
C337  0.1uF  [CAP0402_0-75]  188.65 50.94 270 top
C338  0.1uF  [CAP0402_0-75]  173.34 50.83 0 top
C339  0.1uF  [CAP0402_0-75]  204.43 50.36 90 top
C340  0.1uF  [CAP0201_0-5]  176.07 50.34 180 top
C341  0.1uF  [CAP0201_0-5]  182.47 50.13 90 top
C342  0.1uF  [CAP0402_0-75]  211.23 49.59 270 top
C343  0.1uF  [CAP0201_0-5]  176.07 49.47 180 top
C346  0.1uF  [CAP0402_0-75]  126.14 36.4 180 bottom
C347  0.1uF  [CAP0402_0-75]  117.69 36.3 180 bottom
C348  0.1uF  [CAP0402_0-75]  188.65 48.24 270 top
C349  0.1uF  [CAP0402_0-75]  163.94 47.31 270 top
C350  0.1uF  [CAP0402_0-75]  165.08 47.31 270 top
C351  0.1uF  [CAP0402_0-75]  166.23 47.31 270 top
C352  0.1uF  [CAP0201_0-5]  168.21 46.64 270 top
C353  2.2uF  [CAP0603_1]  181.49 47.07 270 top
C354  0.1uF  [CAP0402_0-75]  180.07 47.02 270 top
C355  0.1uF  [CAP0402_0-75]  67.5 46.82 180 top
C358  0.1uF  [CAP0402_0-75]  188.65 46.18 270 top
C359  0.1uF  [CAP0201_0-5]  169.36 46.64 270 top
C360  0.1uF  [CAP0201_0-5]  171.39 46.64 270 top
C361  0.1uF  [CAP0201_0-5]  170.37 46.64 270 top
C362  0.1uF  [CAP0402_0-75]  79.69 45.39 270 top
C363  0.1uF  [CAP0402_0-75]  80.83 45.39 270 top
C364  0.1uF  [CAP0402_0-75]  81.97 45.39 270 top
C365  0.1uF  [CAP0402_0-75]  65.43 45.22 180 top
C366  0.1uF  [CAP0402_0-75]  188.65 44.05 270 top
C369  1uF  [CAP0402_0-75]  59.28 43.89 270 top
C370  0.1uF  [CAP0402_0-75]  57.74 42.21 180 top
C371  0.1uF  [CAP0402_0-75]  188.65 41.99 270 top
C372  0.1uF  [CAP0402_0-75]  221.12 41.91 90 top
C373  0.1uF  [CAP0402_0-75]  84.23 41.78 0 top
C376  0.1uF  [CAP0402_0-75]  46.17 40.64 180 top
C377  220pF  [CAP0402_0-75]  24.4 40.1 90 top
C378  0.1uF  [CAP0402_0-75]  26.05 40.1 90 top
C379  220pF  [CAP0402_0-75]  27.32 40.1 90 top
C380  0.1uF  [CAP0402_0-75]  188.65 39.86 270 top
C381  0.1uF  [CAP0402_0-75]  84.11 38.82 90 top
C382  0.1uF  [CAP0402_0-75]  79.79 38.31 180 top
C383  0.1uF  [CAP0402_0-75]  159.84 38.22 90 top
C384  0.1uF  [CAP0402_0-75]  160.98 38.22 90 top
C385  0.1uF  [CAP0402_0-75]  162.13 38.22 90 top
C386  0.1uF  [CAP0402_0-75]  188.65 37.8 270 top
C387  0.1uF  [CAP0402_0-75]  169.83 37.6 180 top
C388  0.1uF  [CAP0402_0-75]  171.89 37.6 180 top
C389  0.1uF  [CAP0402_0-75]  174.15 37.6 180 top
C390  0.1uF  [CAP0402_0-75]  176.21 37.6 180 top
C391  0.1uF  [CAP0402_0-75]  178.46 37.6 180 top
C392  0.1uF  [CAP0402_0-75]  180.53 37.6 180 top
C393  0.1uF  [CAP0402_0-75]  84.11 36.15 90 top
C394  0.1uF  [CAP0402_0-75]  92.94 36.05 270 top
C395  0.1uF  [CAP0402_0-75]  188.65 35.67 270 top
C396  0.1uF  [CAP0402_0-75]  80.17 35.26 270 top
C397  0.1uF  [CAP0402_0-75]  75.41 35 180 top
C398  0.1uF  [CAP0402_0-75]  188.65 33.61 270 top
C399  0.01uF  [CAP0402_0-75]  113.6 33.15 180 top
C400  0.1uF  [CAP0402_0-75]  163.51 32.42 90 top
C401  0.1uF  [CAP0402_0-75]  46.82 32.09 270 top
C402  0.1uF  [CAP0402_0-75]  154.09 31.94 180 top
C403  0.1uF  [CAP0402_0-75]  156.15 31.94 180 top
C404  0.1uF  [CAP0402_0-75]  227.76 31.53 270 top
C405  0.01uF  [CAP0402_0-75]  157.92 31.47 90 top
C406  1uF  [CAP0402_0-75]  48.57 31.31 0 top
C407  10uF  [CAP0603_1-25]  215.93 31.22 0 top
C408  4.7uF  [CAP0603_1]  119.69 31.01 180 top
C409  1uF  [CAP0402_0-75]  86.04 29.54 270 top
C410  0.1uF  [CAP0402_0-75]  215.93 29.45 0 top
C411  10uF  [CAP0603_1-25]  37.78 29.32 270 top
C412  0.1uF  [CAP0402_0-75]  39.18 29.32 270 top
C413  0.1uF  [CAP0402_0-75]  42.48 29.32 270 top
C414  10uF  [CAP0603_1-25]  43.87 29.32 270 top
C415  0.1uF  [CAP0402_0-75]  130.01 28.96 90 top
C416  10uF  [CAP0805_1-5]  111.95 28.86 270 top
C417  0.1uF  [CAP0402_0-75]  113.6 28.86 90 top
C418  0.1uF  [CAP0402_0-75]  118.93 28.86 90 top
C419  1uF  [CAP0402_0-75]  120.2 28.86 270 top
C420  0.1uF  [CAP0402_0-75]  225.12 28.73 180 top
C421  0.1uF  [CAP0402_0-75]  230.69 28.43 90 top
C422  0.1uF  [CAP0402_0-75]  73.14 28.33 270 top
C423  0.1uF  [CAP0402_0-75]  74.28 28.33 270 top
C424  0.1uF  [CAP0402_0-75]  98.79 28.33 270 top
C425  0.1uF  [CAP0402_0-75]  99.93 28.33 270 top
C426  0.1uF  [CAP0402_0-75]  166.81 28.08 180 top
C427  0.1uF  [CAP0402_0-75]  123.88 25.65 270 top
C428  0.1uF  [CAP0402_0-75]  192.04 27.12 90 top
C429  0.1uF  [CAP0402_0-75]  218.14 27.12 90 top
C430  0.1uF  [CAP0402_0-75]  189.54 27.12 90 top
C431  0.1uF  [CAP0402_0-75]  215.64 27.12 90 top
C432  10uF  [CAP0805_1-5]  18.88 26.77 270 top
C433  0.1uF  [CAP0402_0-75]  51.42 26.53 0 top
C434  2200pF  [CAP0805_1-5]  33.59 26.26 90 top
C435  0.1uF  [CAP0402_0-75]  166.81 26.18 0 top
C436  0.1uF  [CAP0402_0-75]  77.01 26.09 180 top
C437  0.1uF  [CAP0402_0-75]  102.67 26.09 180 top
C438  2.2uF  [CAP0603_1]  171.23 25.82 0 top
C439  0.01uF  [CAP0402_0-75]  113.6 25.71 180 top
C440  3.3pF  [CAP0402_0-75]  26.53 25.64 180 top
C441  0.1uF  [CAP0402_0-75]  204.05 25.09 0 top
C442  0.1uF  [CAP0402_0-75]  77.01 24.95 180 top
C443  0.1uF  [CAP0402_0-75]  102.67 24.95 180 top
C444  0.1uF  [CAP0402_0-75]  28.15 24.82 270 top
C445  4.7uF  [CAP0603_1]  182.78 24.65 270 top
C446  0.1uF  [CAP0402_0-75]  171.17 24.52 0 top
C447  0.01uF  [CAP0402_0-75]  37.45 24.26 270 top
C448  0.1uF  [CAP0402_0-75]  23.92 24.19 180 top
C449  4.7uF  [CAP0603_1]  208.18 23.95 0 top
C450  0.1uF  [CAP0402_0-75]  20.16 23.7 0 top
C451  0.1uF  [CAP0402_0-75]  139.76 23.68 0 top
C452  22pF  [CAP0402_0-75]  33.41 23.42 270 top
C453  4.7uF  [CAP0805_1-5]  166.66 22.84 90 top
C454  0.1uF  [CAP0402_0-75]  168.44 22.77 90 top
C455  2.2uF  [CAP0402_0-75]  139.76 22.51 0 top
C456  0.1uF  [CAP0402_0-75]  182.67 22.18 270 top
C457  0.1uF  [CAP0402_0-75]  208.77 22.18 270 top
C458  0.1uF  [CAP0402_0-75]  198.14 21.97 270 top
C459  2.2uF  [CAP0805_1-5]  22.24 21.91 180 top
C460  0.1uF  [CAP0402_0-75]  224.18 21.71 270 top
C461  10uF  [CAP0805_1-5]  111.95 21.42 270 top
C462  0.1uF  [CAP0402_0-75]  113.6 21.42 90 top
C463  0.1uF  [CAP0402_0-75]  118.93 21.42 90 top
C464  1uF  [CAP0402_0-75]  120.2 21.42 270 top
C465  0.1uF  [CAP0402_0-75]  32.15 21.22 0 top
C466  0.1uF  [CAP0402_0-75]  29.52 21.17 0 top
C467  0.1uF  [CAP0402_0-75]  57.03 21.14 0 top
C468  4.7uF  [CAP0603_1]  135.47 20.91 90 top
C469  0.1uF  [CAP0402_0-75]  136.86 20.91 90 top
C470  1uF  [CAP0402_0-75]  98.11 20.2 270 top
C471  1uF  [CAP0402_0-75]  99.61 20.2 270 top
C472  1uF  [CAP0402_0-75]  101.11 20.2 270 top
C473  0.1uF  [CAP0402_0-75]  41.52 19.96 270 top
C474  0.1uF  [CAP0402_0-75]  30.2 19.77 0 top
C475  10uF  [CAP0805_1-5]  54.16 19.72 90 top
C476  1uF  [CAP0402_0-75]  72.46 19.57 270 top
C477  1uF  [CAP0402_0-75]  73.96 19.57 270 top
C478  1uF  [CAP0402_0-75]  75.46 19.57 270 top
C479  2.2uF  [CAP0805_1-5]  22.24 19.53 180 top
C480  0.1uF  [CAP0402_0-75]  182.29 19.43 180 top
C481  0.1uF  [CAP0402_0-75]  208.39 19.43 180 top
C482  0.1uF  [CAP0402_0-75]  51.24 19.34 90 top
C483  1uF  [CAP0402_0-75]  52.38 19.34 90 top
C484  10uF  [CAP0805_1-5]  44.11 19.31 180 top
C485  4.7uF  [CAP0603_1]  117.18 18.16 180 top
C486  4.7uF  [CAP0603_1]  120.99 18.16 180 top
C487  0.1uF  [CAP0402_0-75]  20.16 17.74 0 top
C488  22pF  [CAP0402_0-75]  33.41 17.31 270 top
C489  0.1uF  [CAP0402_0-75]  197.71 17.13 90 top
C490  0.1uF  [CAP0402_0-75]  223.8 17.13 90 top
C491  0.01uF  [CAP0402_0-75]  37.24 17.13 90 top
C492  0.1uF  [CAP0402_0-75]  117.18 16.89 180 top
C493  0.1uF  [CAP0402_0-75]  120.99 16.89 180 top
C494  0.1uF  [CAP0402_0-75]  130.62 16.54 180 top
C495  0.1uF  [CAP0402_0-75]  140.42 16.54 180 top
C496  0.1uF  [CAP0402_0-75]  150.22 16.54 180 top
C497  0.1uF  [CAP0402_0-75]  160.03 16.54 180 top
C498  0.1uF  [CAP0402_0-75]  169.83 16.54 180 top
C499  3.3pF  [CAP0402_0-75]  25.87 15.86 180 top
C500  0.1uF  [CAP0402_0-75]  182.16 15.63 180 top
C501  0.1uF  [CAP0402_0-75]  204.64 15.46 0 top
C502  0.1uF  [CAP0402_0-75]  208.39 15.43 180 top
C503  10uF  [CAP0805_1-5]  18.88 14.67 90 top
C504  1uF  [CAP0402_0-75]  38.02 14.58 90 top
C505  0.1uF  [CAP0402_0-75]  39.29 14.58 90 top
C506  2200pF  [CAP0805_1-5]  33.59 14.45 90 top
C507  0.1uF  [CAP0402_0-75]  54.42 14.38 90 top
C508  0.1uF  [CAP0402_0-75]  31.76 12.11 0 top
C509  18pF  [CAP0402_0-75]  210.44 11.31 270 top
C510  0.1uF  [CAP0402_0-75]  187.9 11.22 270 top
C511  0.1uF  [CAP0402_0-75]  214 11.22 270 top
C512  0.1uF  [CAP0402_0-75]  190.54 11.18 270 top
C513  0.1uF  [CAP0402_0-75]  192.04 11.18 270 top
C514  0.1uF  [CAP0402_0-75]  193.19 11.18 270 top
C515  0.1uF  [CAP0402_0-75]  216.64 11.18 270 top
C516  0.1uF  [CAP0402_0-75]  218.14 11.18 270 top
C517  0.1uF  [CAP0402_0-75]  219.28 11.18 270 top
C518  10uF  [CAP0805_1-5]  24.06 11.06 180 top
C519  18pF  [CAP0402_0-75]  185.89 10.3 270 top
C520  0.1uF  [CAP0402_0-75]  39.29 10.27 90 top
C521  0.1uF  [CAP0402_0-75]  176.29 19.38 180 top
C522  0.1uF  [CAP0402_0-75]  24.06 9.41 180 top
C523  18pF  [CAP0402_0-75]  210.42 9.27 90 top
C524  0.1uF  [CAP0402_0-75]  60.51 9.18 270 top
C525  18pF  [CAP0402_0-75]  185.87 8.26 90 top
C526  1uF  [CAP0402_0-75]  38.02 8.15 270 top
C527  0.1uF  [CAP0402_0-75]  39.29 8.15 270 top
C528  0.1uF  [CAP0402_0-75]  54.24 7.66 270 top
C529  1uF  [CAP0402_0-75]  55.51 7.66 270 top
C530  4700pF  [CAP0402_0-75]  124.03 7.57 0 top
C531  10uF  [CAP0805_1-5]  57.31 7.55 270 top
C532  0.1uF  [CAP0402_0-75]  127.85 7.27 270 top
C533  0.1uF  [CAP0402_0-75]  137.65 7.27 270 top
C534  0.1uF  [CAP0402_0-75]  147.46 7.27 270 top
C535  0.1uF  [CAP0402_0-75]  157.26 7.27 270 top
C536  0.1uF  [CAP0402_0-75]  167.06 7.27 270 top
C537  0.1uF  [CAP0402_0-75]  117.79 7.24 90 top
C538  4700pF  [CAP0402_0-75]  133.36 6.92 270 top
C539  4700pF  [CAP0402_0-75]  143.16 6.92 270 top
C540  4700pF  [CAP0402_0-75]  152.97 6.92 270 top
C541  4700pF  [CAP0402_0-75]  162.77 6.92 270 top
C542  4700pF  [CAP0402_0-75]  172.58 6.92 270 top
C543  0.1uF  [CAP0402_0-75]  24.06 6.1 180 top
C544  10uF  [CAP0805_1-5]  38.34 5.93 180 top
C545  10uF  [CAP0805_1-5]  24.06 4.45 180 top
C546  10uF  [CAP0603_1-25]  176.34 186.6 270 bottom
C547  1000pF  [CAP1206_1-75]  33.51 185.49 0 bottom
C548  0.1uF  [CAP0402_0-75]  178.9 184.9 0 bottom
C549  150uF_10V  [CAPT7343D_3-25]  136.18 183.33 0 bottom
C550  0.1uF  [CAP0402_0-75]  11.24 180.42 90 bottom
C551  0.01uF  [CAP0402_0-75]  12.62 180.42 90 bottom
C552  0.1uF  [CAP0402_0-75]  24.3 180.21 90 bottom
C553  12pF  [CAP0402_0-75]  21.26 179.66 180 bottom
C554  12pF  [CAP0402_0-75]  19.22 179.66 0 bottom
C555  10uF  [CAP0805_1-5]  144.46 178.24 270 bottom
C556  0.1uF  [CAP0402_0-75]  142.71 178.24 270 bottom
C557  0.1uF  [CAP0402_0-75]  57.46 178.04 90 bottom
C558  10uF  [CAP0805_1-5]  59.22 177.78 90 bottom
C559  10uF  [CAP0805_1-5]  190.64 176.96 270 bottom
C560  10uF  [CAP0805_1-5]  126.67 175.93 0 bottom
C561  0.1uF  [CAP0402_0-75]  138.55 175.92 270 bottom
C562  0.1uF  [CAP0402_0-75]  69.41 175.62 270 bottom
C563  0.1uF  [CAP0402_0-75]  65.91 175.62 270 bottom
C564  0.1uF  [CAP0402_0-75]  64.75 175.62 270 bottom
C565  10uF  [CAP0805_1-5]  108.52 175.29 0 bottom
C566  10uF  [CAP0805_1-5]  99.88 173.94 270 bottom
C567  1uF  [CAP0402_0-75]  61.96 173.79 0 bottom
C568  0.1uF  [CAP0402_0-75]  172.4 173.68 270 bottom
C569  0.1uF  [CAP0402_0-75]  73.35 173.68 180 bottom
C570  0.1uF  [CAP0402_0-75]  108.52 173.64 180 bottom
C571  0.1uF  [CAP0402_0-75]  181.26 173.03 0 bottom
C572  0.01uF  [CAP0402_0-75]  104.25 172.83 270 bottom
C573  0.1uF  [CAP0402_0-75]  61.96 172.65 0 bottom
C574  0.1uF  [CAP0402_0-75]  160.55 172.19 0 bottom
C575  0.1uF  [CAP0402_0-75]  158.91 172.09 270 bottom
C576  0.01uF  [CAP0402_0-75]  26.75 169.43 90 bottom
C577  1uF  [CAP0402_0-75]  135.31 169.2 90 bottom
C578  0.1uF  [CAP0402_0-75]  134.04 169.2 270 bottom
C579  0.1uF  [CAP0402_0-75]  128.84 169.2 270 bottom
C580  10uF  [CAP0805_1-5]  127.19 169.2 90 bottom
C581  0.1uF  [CAP0402_0-75]  108.52 168.43 180 bottom
C582  4.7uF  [CAP0603_1]  106.37 167.52 90 bottom
C583  1uF  [CAP0402_0-75]  108.52 167.16 0 bottom
C584  4.7uF  [CAP0603_1]  134.93 167.05 180 bottom
C585  0.1uF  [CAP0402_0-75]  141.61 166.96 180 bottom
C586  0.1uF  [CAP0402_0-75]  190.81 166.22 180 bottom
C587  0.1uF  [CAP0402_0-75]  188.75 166.22 180 bottom
C588  0.01uF  [CAP0402_0-75]  129.64 164.93 0 bottom
C589  1uF  [CAP0402_0-75]  60.96 164.48 90 bottom
C590  0.1uF  [CAP0402_0-75]  67.91 164.32 90 bottom
C591  0.1uF  [CAP0402_0-75]  66.15 164.32 90 bottom
C592  0.1uF  [CAP0402_0-75]  65.01 164.32 90 bottom
C593  1uF  [CAP0402_0-75]  63.86 164.32 90 bottom
C594  0.1uF  [CAP0402_0-75]  70.91 164.19 90 bottom
C595  0.1uF  [CAP0402_0-75]  33.39 164.16 180 bottom
C596  0.1uF  [CAP0402_0-75]  28.84 164.16 180 bottom
C597  10uF  [CAP0603_1-25]  29.02 161.42 90 bottom
C598  0.01uF  [CAP0402_0-75]  17.08 160.69 180 bottom
C599  0.01uF  [CAP0402_0-75]  12.86 160.27 270 bottom
C600  0.1uF  [CAP0402_0-75]  141.77 157.97 90 bottom
C601  10uF  [CAP0603_1-25]  140.24 157.97 90 bottom
C602  0.22uF  [CAP1206_1-25]  232.25 157.92 0 bottom
C603  0.1uF  [CAP0603_1]  232.25 155.89 0 bottom
C604  10uF  [CAP0603_1-25]  137.19 155.29 90 bottom
C605  0.1uF  [CAP0402_0-75]  138.59 155.24 90 bottom
C606  10uF  [CAP0603_1-25]  152.46 155.23 180 bottom
C607  0.1uF  [CAP0603_1]  232.25 154.36 0 bottom
C608  0.1uF  [CAP0402_0-75]  152.46 153.7 180 bottom
C609  0.1uF  [CAP0402_0-75]  141 153.17 180 bottom
C610  2.2uF  [CAP0402_0-75]  142.96 153.14 0 bottom
C611  0.1uF  [CAP0402_0-75]  18.83 152.46 180 bottom
C612  2.2uF  [CAP0402_0-75]  141 152.03 180 bottom
C613  0.1uF  [CAP0402_0-75]  151.36 151.28 90 bottom
C614  2.2uF  [CAP0402_0-75]  150.09 151.28 90 bottom
C615  0.1uF  [CAP0402_0-75]  148.82 151.28 90 bottom
C616  0.1uF  [CAP0402_0-75]  147.55 151.28 90 bottom
C617  2.2uF  [CAP0402_0-75]  146.28 151.28 90 bottom
C618  0.1uF  [CAP0402_0-75]  145.01 151.28 90 bottom
C619  0.1uF  [CAP0402_0-75]  143.74 151.28 90 bottom
C620  2.2uF  [CAP0402_0-75]  141 150.88 180 bottom
C621  0.22uF  [CAP0201_0-5]  48.4 150.37 90 bottom
C622  0.22uF  [CAP0201_0-5]  47.64 150.37 90 bottom
C623  0.22uF  [CAP0201_0-5]  44.4 150.37 90 bottom
C624  0.22uF  [CAP0201_0-5]  43.64 150.37 90 bottom
C625  0.22uF  [CAP0201_0-5]  40.4 150.37 90 bottom
C626  0.22uF  [CAP0201_0-5]  39.64 150.37 90 bottom
C627  0.22uF  [CAP0201_0-5]  36.4 150.37 90 bottom
C628  0.22uF  [CAP0201_0-5]  35.64 150.37 90 bottom
C629  100uF  [CAP1210_2-75]  173.08 150.35 0 bottom
C630  0.1uF  [CAP0402_0-75]  27.02 150.35 270 bottom
C631  0.1uF  [CAP0402_0-75]  141 149.74 180 bottom
C632  2.2uF  [CAP0402_0-75]  149 148.6 270 bottom
C633  2.2uF  [CAP0402_0-75]  147.86 148.6 270 bottom
C634  0.1uF  [CAP0402_0-75]  146.72 148.6 270 bottom
C635  0.1uF  [CAP0402_0-75]  145.45 147.96 270 bottom
C636  2.2uF  [CAP0402_0-75]  144.31 147.96 270 bottom
C637  0.1uF  [CAP0402_0-75]  143.16 147.96 270 bottom
C638  0.1uF  [CAP0402_0-75]  142.02 147.96 270 bottom
C639  2.2uF  [CAP0402_0-75]  140.88 147.96 270 bottom
C640  2.2uF  [CAP0402_0-75]  139.73 147.96 270 bottom
C641  2.2uF  [CAP0402_0-75]  138.59 147.96 270 bottom
C642  2.2uF  [CAP0402_0-75]  137.45 147.96 270 bottom
C643  0.01uF  [CAP0402_0-75]  212.4 145.07 270 bottom
C650  0.1uF  [CAP0603_1]  207.45 142.15 90 bottom
C654  10uF  [CAP0603_1-25]  29.02 141.1 90 bottom
C655  0.1uF  [CAP0402_0-75]  18.79 140.19 180 bottom
C656  0.1uF  [CAP0201_0-5]  111.05 136.65 90 bottom
C657  0.1uF  [CAP0201_0-5]  110.34 136.65 90 bottom
C658  0.1uF  [CAP0201_0-5]  109.21 136.65 90 bottom
C659  0.1uF  [CAP0201_0-5]  108.5 136.65 90 bottom
C660  0.1uF  [CAP0201_0-5]  107.55 136.65 90 bottom
C661  0.1uF  [CAP0201_0-5]  106.84 136.65 90 bottom
C662  0.1uF  [CAP0201_0-5]  105.71 136.65 90 bottom
C663  0.1uF  [CAP0201_0-5]  105 136.65 90 bottom
C664  0.1uF  [CAP0201_0-5]  104.21 136.65 90 bottom
C665  0.1uF  [CAP0201_0-5]  103.5 136.65 90 bottom
C666  0.1uF  [CAP0603_1]  211.49 136.38 0 bottom
C667  0.1uF  [CAP0603_1]  231.17 135.67 0 bottom
C668  0.1uF  [CAP0402_0-75]  112.86 135.39 0 bottom
C676  0.1uF  [CAP0402_0-75]  116.23 134.02 90 bottom
C678  4.7uF  [CAP1206_2]  231.17 133.59 0 bottom
C679  0.22uF  [CAP0201_0-5]  129.26 132.92 90 bottom
C680  0.22uF  [CAP0201_0-5]  128.25 132.92 90 bottom
C681  15pF  [CAP0402_0-75]  119.62 132.68 0 bottom
C682  10uF  [CAP0805_1-5]  97.19 132.39 270 bottom
C683  0.22uF  [CAP0201_0-5]  129.26 132.24 90 bottom
C684  0.22uF  [CAP0201_0-5]  128.25 132.24 90 bottom
C685  0.1uF  [CAP0402_0-75]  99.69 131.99 180 bottom
C686  0.01uF  [CAP0402_0-75]  89.19 131.81 180 bottom
C687  0.22uF  [CAP0201_0-5]  40.4 130.05 90 bottom
C688  0.22uF  [CAP0201_0-5]  39.64 130.05 90 bottom
C689  0.22uF  [CAP0201_0-5]  36.4 130.05 90 bottom
C690  0.22uF  [CAP0201_0-5]  35.64 130.05 90 bottom
C691  0.1uF  [CAP0402_0-75]  27.02 130.03 270 bottom
C692  0.1uF  [CAP0402_0-75]  20.35 129.99 270 bottom
C693  10uF  [CAP0603_1-25]  18.45 129.93 270 bottom
C694  0.22uF  [CAP0201_0-5]  127.55 129.92 90 bottom
C695  0.22uF  [CAP0201_0-5]  126.54 129.92 90 bottom
C696  0.22uF  [CAP0201_0-5]  127.55 129.24 270 bottom
C697  0.22uF  [CAP0201_0-5]  126.54 129.24 270 bottom
C698  0.1uF  [CAP0402_0-75]  153.5 128.17 180 bottom
C699  0.1uF  [CAP0402_0-75]  151.44 128.17 180 bottom
C700  10uF  [CAP0805_1-5]  91.65 127.54 270 bottom
C701  0.1uF  [CAP0402_0-75]  90 127.54 90 bottom
C702  0.1uF  [CAP0402_0-75]  84.72 127.54 90 bottom
C703  4.7uF  [CAP0603_1]  83.32 127.54 90 bottom
C704  0.1uF  [CAP0402_0-75]  62.96 125.43 270 bottom
C705  10pF  [CAP0402_0-75]  172.73 123.85 90 bottom
C706  0.1uF  [CAP0402_0-75]  90.59 123.91 270 bottom
C707  0.1uF  [CAP0402_0-75]  62.96 123.36 270 bottom
C708  0.1uF  [CAP0402_0-75]  51.21 123.09 270 bottom
C709  0.1uF  [CAP0402_0-75]  156.01 122.45 270 bottom
C710  0.1uF  [CAP0402_0-75]  90.61 122.03 270 bottom
C711  0.1uF  [CAP0402_0-75]  104.98 120.7 0 bottom
C712  0.1uF  [CAP0402_0-75]  109.17 120.6 180 bottom
C713  0.22uF  [CAP0201_0-5]  110.65 120.51 270 bottom
C714  0.1uF  [CAP0402_0-75]  156.01 120.39 270 bottom
C715  0.1uF  [CAP0402_0-75]  51.67 119 0 bottom
C716  0.1uF  [CAP0402_0-75]  90.83 118.65 270 bottom
C717  0.1uF  [CAP0402_0-75]  44.8 118.11 180 bottom
C718  1uF  [CAP0603_1]  117.94 117.74 180 bottom
C719  1uF  [CAP0603_1]  115.4 117.74 0 bottom
C720  0.1uF  [CAP0402_0-75]  90.84 116.82 270 bottom
C721  0.1uF  [CAP0402_0-75]  24.56 115.8 0 bottom
C722  0.1uF  [CAP0402_0-75]  66.37 114.81 0 bottom
C723  0.1uF  [CAP0402_0-75]  64.3 114.81 0 bottom
C724  22uF  [CAP0805_1-25]  129.6 110.65 270 bottom
C725  22uF  [CAP0805_1-25]  126.04 110.65 270 bottom
C726  4.7uF  [CAP0805_1-5#2]  122.49 110.65 270 bottom
C729  4.7uF  [CAP0805_1-5#2]  114.13 110.65 270 bottom
C730  4.7uF  [CAP0805_1-5#2]  111.72 110.65 270 bottom
C731  4.7uF  [CAP0805_1-5#2]  109.3 110.65 270 bottom
C742  22uF  [CAP0805_1-25]  130.23 106.2 270 bottom
C743  22uF  [CAP0805_1-25]  133.79 106.2 270 bottom
C744  22uF  [CAP0805_1-25]  126.68 106.2 270 bottom
C746  4.7uF  [CAP0805_1-5#2]  119.57 106.2 270 bottom
C747  4.7uF  [CAP0805_1-5#2]  116.01 106.2 270 bottom
C749  4.7uF  [CAP0805_1-5#2]  108.8 106.2 270 bottom
C750  4.7uF  [CAP0805_1-5#2]  106.51 106.2 270 bottom
C751  1uF  [CAP0402_0-75]  132.01 105.94 270 bottom
C752  1uF  [CAP0402_0-75]  135.57 105.94 270 bottom
C753  1uF  [CAP0402_0-75]  128.46 105.94 270 bottom
C755  1uF  [CAP0402_0-75]  121.34 105.94 270 bottom
C756  1uF  [CAP0402_0-75]  117.79 105.94 270 bottom
C758  1uF  [CAP0402_0-75]  110.57 105.94 270 bottom
C762  10uF  [CAP0805_1-5#2]  157.72 103.79 90 bottom
C763  4.7uF  [CAP0805_1-5#2]  154.26 103.79 90 bottom
C764  4.7uF  [CAP0805_1-5#2]  150.81 103.79 90 bottom
C765  22uF  [CAP0805_1-25]  146.46 102.54 90 bottom
C766  0.1uF  [CAP0402_0-75]  53.22 103.33 90 bottom
C768  0.1uF  [CAP0402_0-75]  30.12 101.58 0 bottom
C769  0.1uF  [CAP0402_0-75]  178.14 101.55 270 bottom
C770  0.1uF  [CAP0402_0-75]  183.36 101.46 90 bottom
C772  1uF  [CAP0402_0-75]  24.93 100.3 0 bottom
C773  1uF  [CAP0402_0-75]  111.06 100.08 90 bottom
C774  1uF  [CAP0402_0-75]  121.34 100.08 90 bottom
C776  1uF  [CAP0402_0-75]  115.38 100.08 90 bottom
C777  1uF  [CAP0402_0-75]  109.66 100.08 90 bottom
C778  1uF  [CAP0402_0-75]  126.74 100.08 90 bottom
C779  1uF  [CAP0402_0-75]  123.73 100.08 90 bottom
C780  1uF  [CAP0402_0-75]  122.49 100.08 90 bottom
C782  1uF  [CAP0402_0-75]  112.71 100.08 90 bottom
C783  0.01uF  [CAP0402_0-75]  148.01 99.3 180 bottom
C784  0.01uF  [CAP0402_0-75]  145.85 99.3 180 bottom
C785  0.1uF  [CAP0402_0-75]  179.5 99.19 180 bottom
C786  2.2uF  [CAP0402_0-75]  177.48 99.07 0 bottom
C787  0.01uF  [CAP0402_0-75]  153.35 98.9 0 bottom
C788  0.1uF  [CAP0402_0-75]  175.94 98.65 270 bottom
C789  2.2uF  [CAP0402_0-75]  172.47 98.48 180 bottom
C790  0.1uF  [CAP0402_0-75]  174.56 98.21 90 bottom
C791  0.01uF  [CAP0402_0-75]  154.87 97.78 180 bottom
C792  0.01uF  [CAP0402_0-75]  149.53 97.78 0 bottom
C793  0.01uF  [CAP0402_0-75]  152.33 97.79 180 bottom
C794  0.1uF  [CAP0402_0-75]  145.73 94.77 90 bottom
C795  0.01uF  [CAP0402_0-75]  160.97 96.55 270 bottom
C796  0.1uF  [CAP0402_0-75]  199.2 96.25 180 bottom
C797  0.1uF  [CAP0402_0-75]  197.13 96.25 180 bottom
C798  0.1uF  [CAP0402_0-75]  194.36 95.99 180 bottom
C799  0.1uF  [CAP0402_0-75]  192.3 95.99 180 bottom
C800  0.1uF  [CAP0402_0-75]  192.23 81.64 90 bottom
C801  0.1uF  [CAP0402_0-75]  192.23 83.7 90 bottom
C802  0.1uF  [CAP0402_0-75]  179.64 95.79 270 bottom
C803  0.1uF  [CAP0402_0-75]  178.49 95.79 270 bottom
C804  0.1uF  [CAP0402_0-75]  177.35 95.79 270 bottom
C805  0.1uF  [CAP0402_0-75]  67.93 95.64 270 bottom
C806  0.01uF  [CAP0402_0-75]  155.56 94.89 90 bottom
C807  0.1uF  [CAP0402_0-75]  173.51 94.29 270 bottom
C808  1uF  [CAP0402_0-75]  172.37 94.29 270 bottom
C809  10uF  [CAP0603_1-25]  207.82 94.11 0 bottom
C810  10uF  [CAP0603_1-25]  202.36 94.11 180 bottom
C811  10uF  [CAP0603_1]  158.04 93.59 270 bottom
C812  0.1uF  [CAP0402_0-75]  67.93 93.58 270 bottom
C813  1uF  [CAP0402_0-75]  136.48 87.26 0 bottom
C814  0.01uF  [CAP0402_0-75]  145.22 92.84 270 bottom
C815  0.1uF  [CAP0402_0-75]  207.69 92.57 0 bottom
C816  0.1uF  [CAP0402_0-75]  202.35 92.57 180 bottom
C817  0.01uF  [CAP0402_0-75]  156.39 92.57 270 bottom
C818  1uF  [CAP0402_0-75]  136.48 89.34 0 bottom
C819  1uF  [CAP0402_0-75]  136.48 86.24 0 bottom
C820  1uF  [CAP0402_0-75]  136.48 88.3 0 bottom
C821  0.1uF  [CAP0201_0-5]  135.59 104.27 90 bottom
C822  0.1uF  [CAP0201_0-5]  118.32 90.25 225 bottom
C823  0.1uF  [CAP0402_0-75]  67.93 90.59 270 bottom
C824  0.1uF  [CAP0201_0-5]  126.7 90.37 90 bottom
C825  0.1uF  [CAP0201_0-5]  120.84 89.87 0 bottom
C826  0.1uF  [CAP0201_0-5]  113.57 100.08 90 bottom
C827  0.1uF  [CAP0201_0-5]  111.9 89.08 180 bottom
C828  0.1uF  [CAP0201_0-5]  128.33 79.81 90 bottom
C829  0.1uF  [CAP0201_0-5]  122.72 90.17 90 bottom
C830  0.1uF  [CAP0201_0-5]  121.93 90.17 90 bottom
C832  0.1uF  [CAP0201_0-5]  116.31 90.17 90 bottom
